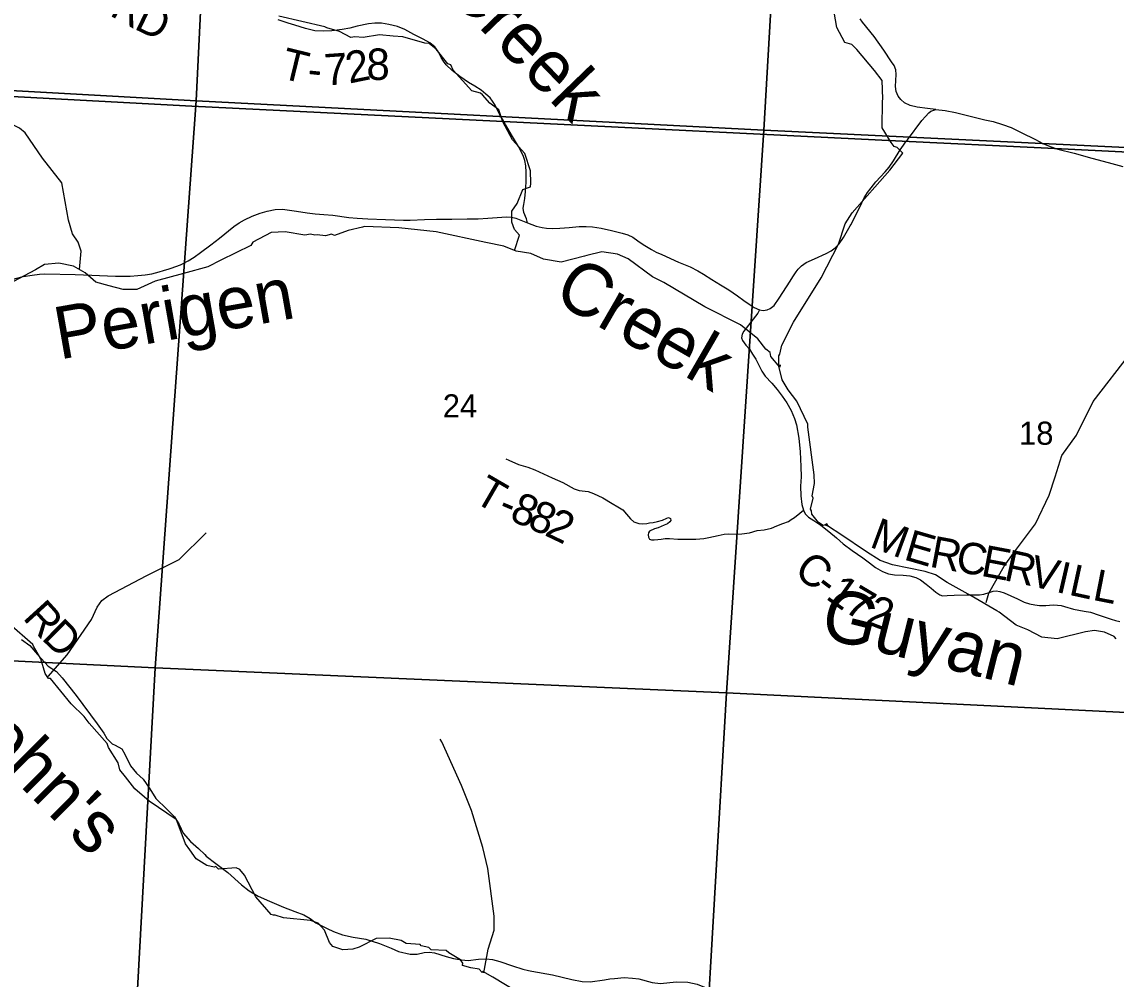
# Model space of a CAD drawing. Extents: x 1878108 to 2183446, y 146837 to 508383.
# Drawn here: x 2019274 to 2029722, y 237108 to 246251 of the extents above; entities that cross this region are included whole.
import ezdxf

# ---------------------------------------------------------------- set-up
doc = ezdxf.new("R2010")
doc.units = 0
for name, color, linetype in [('GM_X_County_Road', 7, 'Continuous'), ('GM_X_County_Road_Text', 7, 'Continuous'), ('GM_X_Minor_River', 7, 'Continuous'), ('GM_X_Minor_River_Text', 7, 'Continuous'), ('GM_X_Section', 7, 'Continuous'), ('GM_X_Section_Text', 7, 'Continuous'), ('GM_X_State_Route', 7, 'Continuous'), ('GM_X_Township', 7, 'Continuous'), ('GM_X_Township_Road', 7, 'Continuous'), ('GM_X_Township_Road_Text', 7, 'Continuous')]:
    doc.layers.add(name, color=color, linetype=linetype)

msp = doc.modelspace()

# ---------------------------------------------------------------- linework, layer by layer
at = {"layer": 'GM_X_County_Road'}
for points in [[(2028001, 245415), (2027921, 245425), (2027824, 245438), (2027755, 245454), (2027703, 245479), (2027667, 245510), (2027641, 245543), (2027623, 245585), (2027617, 245634), (2027622, 245749), (2027618, 245792), (2027603, 245834), (2027578, 245871), (2027505, 245982), (2027412, 246111), (2027302, 246250), (2027278, 246280)], [(2026317, 243500), (2026301, 243469), (2026169, 243297), (2026152, 243268), (2026147, 243233)], [(2026147, 243233), (2026147, 243232), (2026155, 243207), (2026188, 243163), (2026222, 243124), (2026250, 243077), (2026281, 243030), (2026307, 242980), (2026340, 242916), (2026372, 242868), (2026435, 242799), (2026486, 242740), (2026535, 242677), (2026577, 242614), (2026619, 242540), (2026652, 242464), (2026670, 242402), (2026693, 242274), (2026707, 242146), (2026712, 242005), (2026714, 241905), (2026710, 241818), (2026712, 241725), (2026722, 241640), (2026737, 241588), (2026752, 241553), (2026785, 241520), (2026836, 241490), (2026902, 241443), (2026980, 241384), (2027052, 241324), (2027117, 241266), (2027201, 241201), (2027303, 241131), (2027368, 241085), (2027425, 241040), (2027492, 241001), (2027549, 240979), (2027605, 240971), (2027688, 240968), (2027752, 240961), (2027810, 240945), (2027855, 240921), (2027910, 240880), (2027955, 240841), (2028001, 240803), (2028039, 240779), (2028066, 240770), (2028108, 240772), (2028176, 240776), (2028296, 240778), (2028419, 240779), (2028459, 240786), (2028519, 240805), (2028550, 240814), (2028578, 240816), (2028612, 240812), (2028652, 240799), (2028782, 240739), (2028844, 240710), (2028896, 240693), (2028945, 240683), (2028990, 240678), (2029051, 240678), (2029121, 240683), (2029163, 240681), (2029198, 240677), (2029229, 240666), (2029317, 240641), (2029418, 240622), (2029478, 240612), (2029561, 240585), (2029674, 240545), (2029715, 240533), (2029757, 240523)], [(2019272, 240353), (2019349, 240295), (2019422, 240208), (2019526, 240097), (2019604, 240045), (2019660, 239987), (2019792, 239816), (2019993, 239546), (2020057, 239456), (2020087, 239408), (2020135, 239357), (2020164, 239342)], [(2020164, 239342), (2020228, 239309), (2020258, 239257), (2020311, 239145), (2020368, 239074), (2020432, 239017), (2020497, 238926), (2020555, 238834), (2020659, 238732), (2020731, 238658), (2020775, 238584), (2020814, 238503), (2020886, 238422), (2020962, 238357), (2021020, 238299)], [(2021020, 238299), (2021035, 238284), (2021126, 238212), (2021242, 238126), (2021371, 238010), (2021445, 237951), (2021529, 237902), (2021639, 237854), (2021774, 237796), (2021882, 237753), (2021966, 237722), (2022026, 237687), (2022080, 237645), (2022087, 237642)], [(2022087, 237642), (2022188, 237593), (2022251, 237563), (2022336, 237531), (2022438, 237509), (2022558, 237491), (2022690, 237449), (2022801, 237405), (2022869, 237371), (2022983, 237346), (2023048, 237346), (2023114, 237362), (2023167, 237365), (2023215, 237360), (2023327, 237325), (2023396, 237306), (2023471, 237292), (2023537, 237286), (2023633, 237299), (2023707, 237303), (2023769, 237297), (2023838, 237278), (2023960, 237236), (2024059, 237205), (2024112, 237192)], [(2024112, 237192), (2024143, 237184), (2024342, 237149), (2024527, 237105), (2024624, 237087), (2024699, 237083), (2024838, 237100), (2024887, 237110), (2024933, 237114), (2025024, 237125), (2025104, 237119), (2025165, 237110), (2025294, 237077), (2025371, 237068), (2025522, 237081), (2025633, 237080), (2025722, 237061), (2025862, 237002), (2025919, 236983)]]:
    msp.add_lwpolyline(points, dxfattribs=at)
at = {"layer": 'GM_X_Minor_River'}
for points in [[(2019824, 243886), (2019842, 244061), (2019813, 244146), (2019757, 244228), (2019721, 244358), (2019656, 244714), (2019472, 244949), (2019305, 245191), (2019251, 245235), (2019023, 245350), (2018946, 245435), (2018794, 245640), (2018657, 245711), (2018526, 245743), (2018441, 245826), (2018414, 245873), (2018304, 245995), (2018210, 246068), (2017832, 246234), (2017672, 246342)], [(2023979, 244067), (2024025, 244214), (2023979, 244268), (2023951, 244337), (2023953, 244443), (2024004, 244517), (2024058, 244650), (2024132, 244676), (2024134, 244710), (2024132, 244827), (2024076, 244995), (2023960, 245125), (2023868, 245296), (2023830, 245412), (2023744, 245476), (2023674, 245554), (2023654, 245570), (2023570, 245592), (2023392, 245790), (2023370, 245842), (2023342, 245852), (2023231, 245992), (2023163, 246046), (2023123, 246048), (2022913, 246108), (2022819, 246114), (2022690, 246126), (2022534, 246103), (2022452, 246109), (2022416, 246101), (2022308, 246159), (2022186, 246193), (2022167, 246203), (2021729, 246306)], [(2029723, 240357), (2029703, 240381), (2029611, 240423), (2029515, 240439), (2029429, 240425), (2029160, 240360), (2029014, 240373), (2028880, 240443), (2028769, 240489), (2028605, 240613), (2028583, 240627), (2028339, 240769), (2028108, 240895), (2027998, 240969), (2027900, 241003), (2027588, 241064), (2027471, 241106), (2027339, 241188), (2027095, 241354), (2026977, 241430), (2026959, 241458), (2026947, 241446), (2026961, 241440), (2026949, 241442), (2026957, 241452), (2026925, 241440), (2026880, 241470), (2026816, 241548), (2026814, 241582), (2026804, 241596), (2026831, 241703), (2026819, 241723), (2026843, 241843), (2026839, 241925), (2026779, 242379), (2026779, 242409), (2026673, 242627), (2026591, 242736), (2026535, 242832), (2026501, 242964), (2026503, 243060), (2026513, 243077), (2026531, 243163), (2026642, 243384), (2026907, 243808), (2027073, 244127), (2027136, 244322), (2027202, 244427), (2027563, 244835), (2027687, 244996), (2027633, 245050), (2027603, 245060), (2027575, 245100), (2027489, 245240), (2027492, 245495), (2027494, 245515), (2027488, 245692), (2027414, 245788), (2027248, 245988), (2027198, 246034), (2027133, 246054), (2027057, 246198), (2027029, 246345)], [(2022546, 244297), (2022528, 244289), (2022390, 244260), (2022258, 244210), (2022232, 244222), (2022174, 244208), (2022093, 244216), (2022073, 244215), (2022029, 244225), (2021977, 244215), (2021787, 244245), (2021655, 244239), (2021480, 244146), (2021462, 244114), (2021173, 243976), (2021049, 243912), (2020818, 243849), (2020548, 243776), (2020371, 243695), (2020353, 243695), (2020241, 243695), (2020109, 243729), (2019981, 243765), (2019880, 243855), (2019766, 243917), (2019628, 243948), (2019492, 243934), (2019404, 243884), (2019087, 243714)], [(2026504, 242953), (2026515, 242976), (2026513, 242954), (2026427, 243056), (2026419, 243092), (2026379, 243126), (2026301, 243225), (2026135, 243357), (2025794, 243530), (2025404, 243762), (2025295, 243816), (2025063, 243988), (2024961, 244032), (2024813, 244056), (2024668, 244021), (2024648, 244013), (2024424, 243956), (2024254, 243984), (2024133, 244038), (2023993, 244062), (2023875, 244108), (2023703, 244145), (2023230, 244246), (2022873, 244284), (2022546, 244297)], [(2028483, 240707), (2028506, 240796), (2028652, 241052), (2028742, 241176), (2028952, 241456), (2029084, 241732), (2029141, 241907), (2029203, 242109), (2029345, 242303), (2029504, 242625), (2029863, 243089), (2029949, 243164)], [(2019526, 239998), (2019706, 240205), (2019938, 240543), (2019994, 240661), (2020039, 240724), (2020099, 240770), (2020467, 240965), (2020776, 241117), (2021033, 241371)], [(2019744, 239738), (2019548, 239981), (2019528, 239981), (2019496, 240027), (2019454, 240167), (2019386, 240287), (2019378, 240305), (2019154, 240503)], [(2024028, 236970), (2023770, 237128), (2023676, 237182), (2023670, 237172), (2023642, 237202), (2023560, 237216), (2023482, 237237), (2023484, 237262), (2023462, 237292), (2023351, 237358), (2023327, 237382), (2023181, 237387), (2023161, 237411), (2023087, 237427), (2023077, 237439), (2022943, 237447), (2022897, 237477), (2022780, 237499), (2022658, 237496), (2022494, 237414), (2022434, 237393), (2022339, 237389), (2022243, 237421), (2022211, 237459), (2022165, 237575), (2022103, 237643), (2022029, 237669), (2021773, 237693), (2021694, 237720), (2021678, 237720), (2021656, 237726), (2021508, 237895), (2021400, 238101), (2021356, 238155), (2021322, 238171), (2021152, 238159), (2021126, 238185), (2021110, 238178), (2021041, 238192), (2020937, 238258), (2020877, 238342), (2020837, 238401), (2020757, 238615), (2020747, 238633), (2020491, 238809), (2020353, 238925), (2020263, 239041), (2020209, 239107), (2020195, 239174), (2020103, 239320), (2020089, 239360), (2019918, 239552), (2019870, 239618), (2019744, 239738)], [(2023684, 237167), (2023727, 237394), (2023783, 237576), (2023783, 237711), (2023725, 238164), (2023675, 238366), (2023566, 238720), (2023471, 238958), (2023284, 239376), (2023269, 239401)]]:
    msp.add_lwpolyline(points, dxfattribs=at)
at = {"layer": 'GM_X_Section'}
for points in [[(2015798, 251134), (2021200, 250855), (2020937, 245497), (2015391, 245807)], [(2021200, 250855), (2026668, 250565), (2026359, 245218), (2020937, 245497)], [(2026668, 250565), (2026682, 250564), (2032246, 250258), (2031941, 244950), (2026359, 245218)], [(2015391, 245807), (2020937, 245497), (2020547, 240083), (2015123, 240346)], [(2020937, 245497), (2026359, 245218), (2026001, 239844), (2020547, 240083)], [(2026359, 245218), (2031941, 244950), (2031567, 239568), (2026001, 239844)], [(2015123, 240346), (2020547, 240083), (2020250, 234697), (2014808, 234903)], [(2020547, 240083), (2026001, 239844), (2025688, 234438), (2020250, 234697)], [(2026001, 239844), (2031567, 239568), (2031220, 234172), (2025688, 234438)]]:
    msp.add_lwpolyline(points, close=True, dxfattribs=at)
at = {"layer": 'GM_X_State_Route'}
for points in [[(2027184, 244303), (2027189, 244312), (2027274, 244483), (2027316, 244571), (2027347, 244620), (2027382, 244667), (2027428, 244722), (2027517, 244819), (2027554, 244863), (2027598, 244925), (2027659, 245029), (2027691, 245074), (2027719, 245111), (2027730, 245126), (2027866, 245308), (2027902, 245347), (2027934, 245382), (2027954, 245399), (2028001, 245415)], [(2028001, 245415), (2028089, 245406), (2028189, 245386), (2028342, 245349), (2028469, 245316), (2028548, 245299), (2028639, 245272), (2028720, 245242), (2028817, 245196), (2028952, 245128), (2029024, 245091), (2029092, 245062), (2029156, 245040), (2029165, 245036), (2029321, 244996), (2029492, 244951), (2029645, 244909), (2029785, 244870)], [(2020699, 243900), (2020788, 243932), (2020863, 243970), (2020918, 244004), (2020981, 244049), (2021077, 244122), (2021160, 244186), (2021298, 244297), (2021348, 244331), (2021401, 244362), (2021473, 244396), (2021549, 244424), (2021617, 244444), (2021694, 244459), (2021764, 244461), (2021896, 244443), (2021999, 244427), (2022076, 244418), (2022156, 244412), (2022243, 244405), (2022396, 244384), (2022476, 244375), (2022579, 244370), (2022747, 244363), (2022919, 244357), (2022982, 244357), (2023120, 244365), (2023232, 244368), (2023380, 244367), (2023527, 244369), (2023632, 244371), (2023723, 244377), (2023857, 244387), (2023897, 244389), (2023949, 244385), (2023990, 244375), (2024101, 244332), (2024186, 244301), (2024243, 244288), (2024285, 244282), (2024339, 244279), (2024411, 244281), (2024500, 244288), (2024596, 244297), (2024662, 244297), (2024723, 244293), (2024807, 244281), (2024905, 244257), (2025007, 244234), (2025061, 244216), (2025108, 244195), (2025157, 244161), (2025208, 244125), (2025285, 244076), (2025332, 244052), (2025384, 244029), (2025543, 243955), (2025654, 243910), (2025727, 243874), (2025784, 243843), (2025862, 243792), (2025945, 243741), (2026026, 243691), (2026106, 243634), (2026169, 243590), (2026218, 243555), (2026268, 243524), (2026317, 243500), (2026353, 243496), (2026391, 243501), (2026419, 243514), (2026456, 243542), (2026506, 243613), (2026609, 243774)], [(2026609, 243774), (2026637, 243817), (2026666, 243863), (2026688, 243890), (2026717, 243921), (2026762, 243952), (2026841, 243989), (2026955, 244038), (2027003, 244063), (2027040, 244092), (2027078, 244132), (2027118, 244192), (2027184, 244303)], [(2019087, 243762), (2019212, 243800), (2019286, 243818), (2019372, 243833), (2019443, 243843), (2019495, 243846), (2019782, 243838), (2019941, 243831), (2020017, 243829), (2020167, 243824), (2020309, 243823), (2020383, 243828), (2020450, 243835), (2020515, 243846), (2020584, 243863), (2020628, 243876), (2020681, 243893), (2020699, 243900)]]:
    msp.add_lwpolyline(points, dxfattribs=at)
at = {"layer": 'GM_X_Township'}
for points in [[(2037712, 249015), (2037354, 244623), (2033284, 244833), (2031899, 244904), (2029007, 245047), (2027678, 245113), (2023806, 245304), (2020898, 245447), (2015331, 245746), (2011114, 245960), (2009980, 246018), (2010027, 246281)], [(2008888, 227673), (2009016, 229762), (2009205, 232852), (2009662, 240602), (2009980, 246018), (2011114, 245960), (2015331, 245746), (2020898, 245447), (2023806, 245304), (2027678, 245113), (2029007, 245047), (2031899, 244904), (2033284, 244833), (2037354, 244623), (2037219, 242509), (2037025, 239474), (2036924, 237810), (2036687, 233905), (2036623, 232849), (2036493, 230741), (2036351, 228419), (2036235, 226946)]]:
    msp.add_lwpolyline(points, dxfattribs=at)
at = {"layer": 'GM_X_Township_Road'}
for points in [[(2023863, 245321), (2023852, 245340), (2023826, 245390), (2023792, 245457), (2023769, 245495), (2023745, 245525), (2023705, 245562), (2023659, 245599), (2023599, 245637), (2023538, 245672), (2023457, 245729), (2023384, 245788), (2023327, 245842), (2023301, 245876), (2023279, 245911), (2023250, 245968), (2023217, 246012), (2023169, 246051), (2023106, 246086), (2023017, 246132), (2022932, 246179), (2022861, 246207), (2022779, 246227), (2022709, 246239), (2022643, 246239), (2022585, 246233), (2022477, 246210), (2022406, 246191), (2022331, 246177), (2022233, 246166), (2022157, 246164), (2022071, 246166), (2021981, 246187), (2021880, 246220), (2021818, 246238), (2021720, 246270)], [(2024101, 244332), (2024093, 244370), (2024068, 244432), (2024062, 244473), (2024066, 244507), (2024077, 244565), (2024084, 244631), (2024089, 244719), (2024089, 244816), (2024086, 244876), (2024076, 244927), (2024061, 244975), (2024015, 245061), (2023949, 245172), (2023893, 245270), (2023875, 245300), (2023863, 245321)], [(2023895, 242078), (2023923, 242064), (2024017, 242024), (2024106, 241999), (2024172, 241972), (2024338, 241895), (2024441, 241852), (2024547, 241792), (2024597, 241775), (2024683, 241767), (2024731, 241746), (2024820, 241706), (2024912, 241652), (2024966, 241618), (2025012, 241592), (2025046, 241549), (2025086, 241504), (2025119, 241476), (2025146, 241466), (2025166, 241459), (2025197, 241458), (2025242, 241460), (2025266, 241465), (2025302, 241471), (2025345, 241478), (2025390, 241492), (2025431, 241510), (2025449, 241517), (2025467, 241508), (2025472, 241490), (2025461, 241476), (2025440, 241458), (2025406, 241445), (2025351, 241420), (2025315, 241408), (2025267, 241388), (2025256, 241372), (2025254, 241353), (2025259, 241330), (2025267, 241310), (2025287, 241305), (2025312, 241305), (2025346, 241308), (2025378, 241311), (2025418, 241317), (2025458, 241317), (2025536, 241312), (2025635, 241309), (2025708, 241311), (2025787, 241316), (2025835, 241327), (2025922, 241345), (2025979, 241357), (2026024, 241360), (2026095, 241358), (2026148, 241360), (2026223, 241372), (2026296, 241392), (2026363, 241399), (2026431, 241415), (2026484, 241437), (2026541, 241460), (2026593, 241480), (2026621, 241498), (2026650, 241518), (2026701, 241559), (2026737, 241588)]]:
    msp.add_lwpolyline(points, dxfattribs=at)

# ---------------------------------------------------------------- texts
at = {"layer": 'GM_X_County_Road_Text'}
for s, rotation, p in [('M', 339.67, (2027358, 241240)), ('E', 343.7296, (2027685, 241119)), ('R', 349.4099, (2027932, 241049)), ('C', 350.5171, (2028181, 241002)), ('E', 349.3137, (2028422, 240962)), ('C', 321.9763, (2026634, 240983)), ('R', 347.667, (2028641, 240921)), ('V', 347.0302, (2028880, 240869)), ('I', 347.0574, (2029138, 240809)), ('L', 347.6943, (2029261, 240781)), ('1', 324.6859, (2026939, 240748)), ('L', 348.934, (2029488, 240732)), ('-', 322.995, (2026832, 240828)), ('7', 329.3821, (2027112, 240627)), ('R', 312.3317, (2019275, 240555)), ('2', 338.7231, (2027319, 240509)), ('D', 315.5227, (2019453, 240360))]:
    msp.add_text(s, height=300, rotation=rotation, dxfattribs=at).set_placement(p)
at = {"layer": 'GM_X_Minor_River_Text'}
for s, height, rotation, p in [('Creek', 500, 314.0019, (2023291, 246553)), ('Creek', 500, 330.0049, (2024330, 243600)), ('Perigen', 500, 10.0083, (2019632, 243025)), ('Guyan', 500, 346.0032, (2026879, 240378)), ("John's", 499.9, 315.0035, (2018592, 239613))]:
    msp.add_text(s, height=height, rotation=rotation, dxfattribs=at).set_placement(p)
at = {"layer": 'GM_X_Section_Text'}
for s, p in [('24', (2023293, 242473)), ('18', (2028795, 242212))]:
    msp.add_text(s, height=221, rotation=0, dxfattribs=at).set_placement(p)
at = {"layer": 'GM_X_Township_Road_Text'}
for s, rotation, p in [('R', 330.8612, (2020103, 246318)), ('D', 334.4086, (2020336, 246189)), ('T', 346.3411, (2021731, 245717)), ('7', 3.9594, (2022172, 245643)), ('2', 11.512, (2022399, 245661)), ('8', 359.9349, (2022564, 245697)), ('-', 354.1829, (2021993, 245656)), ('T', 329.8543, (2023575, 241676)), ('-', 337.0685, (2023806, 241545)), ('8', 336.7416, (2023919, 241497)), ('8', 336.3405, (2024088, 241425)), ('2', 334.5195, (2024255, 241352))]:
    msp.add_text(s, height=300, rotation=rotation, dxfattribs=at).set_placement(p)

doc.saveas('drawing.dxf')
